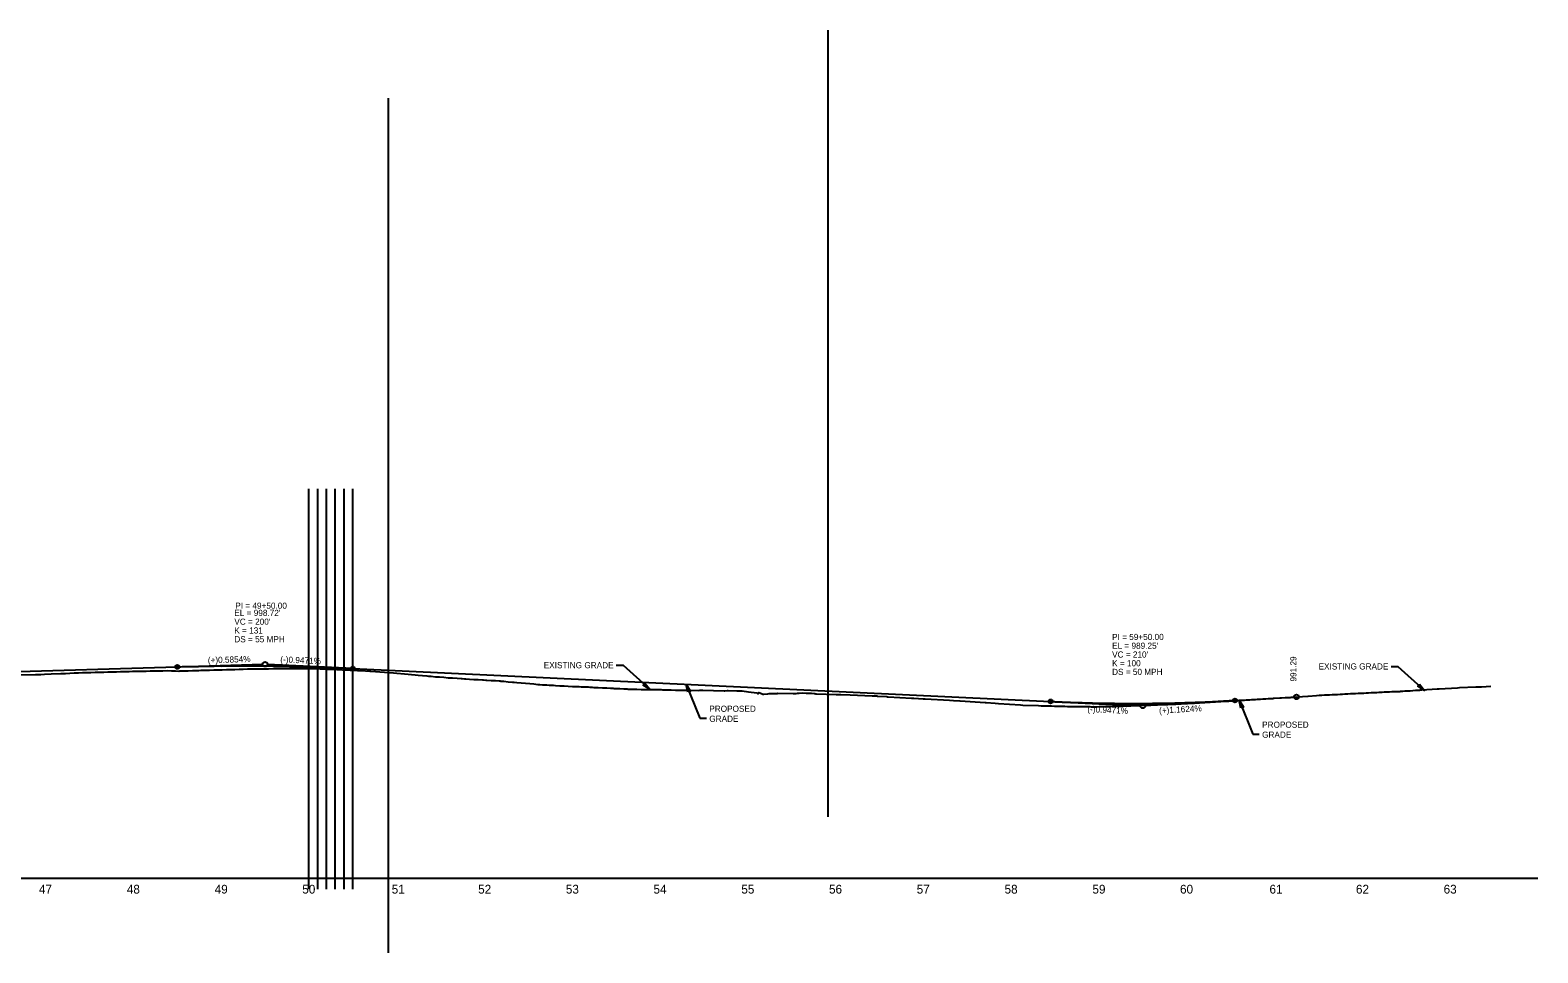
# Model space of a CAD drawing. Extents: x 1615624 to 1632571, y 894455 to 913418.
# Drawn here: x 1627212 to 1628930, y 901249 to 902300 of the extents above; entities that cross this region are included whole.
import ezdxf

# ---------------------------------------------------------------- set-up
doc = ezdxf.new("R2010")
doc.units = 0
for name, color, linetype in [('Default', 7, 'Continuous'), ('Exist Profile Cell', 7, 'Continuous'), ('Exist Vertical Profile Ground Line', 7, 'Continuous'), ('Exist Vertical Profile Horizontal Axis Label Major', 7, 'Continuous'), ('Prop Terminator CELL', 7, 'Continuous'), ('Prop Vertical Profile Curve Label', 7, 'Continuous'), ('Prop Vertical Profile Grade', 7, 'Continuous'), ('Prop Vertical Profile Grade Label', 7, 'Continuous'), ('Prop VPI Ditch Grade Right Label', 7, 'Continuous'), ('Prop VPI Label', 7, 'Continuous')]:
    doc.layers.add(name, color=color, linetype=linetype)

msp = doc.modelspace()

# ---------------------------------------------------------------- linework, layer by layer
at = {"layer": 'Default'}
for p, q in [((1628121.2, 902300.3), (1628121.2, 901404.2)), ((1627620.1, 902222.8), (1627620.1, 901249.4))]:
    msp.add_line(p, q, dxfattribs=at)
at = {"layer": 'Exist Profile Cell'}
for q in [(1628880.1, 901334.4), (1628929.9, 901334.4)]:
    msp.add_line((1623529.9, 901334.4), q, dxfattribs=at)
at = {"layer": 'Exist Vertical Profile Ground Line'}
msp.add_lwpolyline([(1627201.1, 901566.1), (1627218.2, 901566.6), (1627224.4, 901566.6), (1627228.7, 901566.8), (1627236.2, 901567), (1627247.2, 901567.4), (1627247.9, 901567.4), (1627252.7, 901567.7), (1627257.5, 901568), (1627262.3, 901568.3), (1627263.3, 901568.4), (1627263.7, 901568.4), (1627267.2, 901568.5), (1627272, 901568.6), (1627275.1, 901568.7), (1627276.8, 901568.7), (1627281.6, 901568.8), (1627286.4, 901569), (1627291.3, 901569.1), (1627296.3, 901569.2), (1627300.9, 901569.4), (1627305.7, 901569.5), (1627310.5, 901569.6), (1627315.3, 901569.8), (1627320.2, 901569.9), (1627323.6, 901569.9), (1627325, 901570), (1627328.9, 901570.1), (1627329.8, 901570.1), (1627334.6, 901570.2), (1627339.4, 901570.3), (1627344.5, 901570.4), (1627349.1, 901570.5), (1627351, 901570.5), (1627352.4, 901570.5), (1627353.9, 901570.5), (1627358.7, 901570.6), (1627363.5, 901570.7), (1627368.5, 901570.8), (1627373.2, 901570.6), (1627378, 901570.5), (1627381.7, 901570.4), (1627382.8, 901570.5), (1627384.3, 901570.5), (1627387.6, 901570.6), (1627392.4, 901570.7), (1627397.3, 901570.8), (1627402.1, 901571), (1627404.3, 901571), (1627406.9, 901571.2), (1627411.7, 901571.4), (1627412.1, 901571.4), (1627415.2, 901571.5), (1627416.5, 901571.5), (1627421.4, 901571.6), (1627423.9, 901571.7), (1627426.2, 901571.7), (1627430.1, 901571.8), (1627431, 901571.8), (1627435.8, 901572), (1627440.6, 901572.1), (1627445.4, 901572.3), (1627450.3, 901572.5), (1627454.5, 901572.6), (1627455.1, 901572.6), (1627459.9, 901572.7), (1627464.7, 901572.8), (1627467.5, 901572.9), (1627468.9, 901572.9), (1627469.5, 901572.9), (1627474.4, 901572.9), (1627479.2, 901573), (1627484, 901573), (1627488.6, 901573.1), (1627497.6, 901573.2), (1627504.5, 901573.2), (1627512.7, 901573.1), (1627519.1, 901573.1), (1627532.2, 901573.1), (1627542.8, 901572.8), (1627551.2, 901572.5), (1627555, 901572.4), (1627568, 901571.9), (1627585.2, 901571.1), (1627587, 901571), (1627594.2, 901570.5), (1627599.2, 901570.2), (1627600.6, 901570.1), (1627626.3, 901568.3), (1627629.9, 901568.1), (1627638.9, 901567.2), (1627651, 901566.1), (1627654.4, 901565.8), (1627659.3, 901565.3), (1627664.1, 901564.8), (1627666, 901564.7), (1627669, 901564.4), (1627673.9, 901563.9), (1627674.8, 901563.9), (1627678.8, 901563.6), (1627683.7, 901563.2), (1627688.6, 901562.8), (1627693.4, 901562.5), (1627698.6, 901562.1), (1627703.2, 901561.8), (1627704.3, 901561.7), (1627707.2, 901561.5), (1627708.1, 901561.4), (1627708.8, 901561.4), (1627713, 901561.1), (1627717.9, 901560.8), (1627722.8, 901560.6), (1627727.6, 901560.3), (1627728.7, 901560.2), (1627731.3, 901560), (1627732.5, 901560), (1627737.4, 901559.7), (1627740.7, 901559.5), (1627742.3, 901559.4), (1627746.5, 901559.1), (1627747.2, 901559.1), (1627747.6, 901559.1), (1627748.7, 901559), (1627752.1, 901558.7), (1627757, 901558.2), (1627761.8, 901557.7), (1627762.3, 901557.7), (1627763.1, 901557.6), (1627763.7, 901557.6), (1627766.7, 901557.3), (1627771.6, 901556.9), (1627776.5, 901556.4), (1627781.4, 901556), (1627786.3, 901555.6), (1627790.7, 901555.2), (1627791.1, 901555.1), (1627791.5, 901555.1), (1627793, 901555), (1627796, 901554.8), (1627800.9, 901554.5), (1627803.7, 901554.3), (1627805.8, 901554.2), (1627807.6, 901554.2), (1627808.6, 901554.1), (1627810.7, 901554), (1627815.6, 901553.7), (1627820.5, 901553.4), (1627825.3, 901553.1), (1627830.2, 901552.8), (1627831.8, 901552.7), (1627834.4, 901552.6), (1627835.1, 901552.6), (1627837.7, 901552.6), (1627840, 901552.5), (1627844.9, 901552.3), (1627846.8, 901552.2), (1627848, 901552.2), (1627849.8, 901552.1), (1627850.8, 901552), (1627852.5, 901551.9), (1627854.6, 901551.8), (1627859.5, 901551.6), (1627864.4, 901551.4), (1627869.3, 901551.2), (1627873.5, 901551), (1627874.2, 901550.9), (1627876.6, 901550.7), (1627877.7, 901550.6), (1627879.1, 901550.6), (1627880.8, 901550.5), (1627884, 901550.4), (1627888.8, 901550.2), (1627889.3, 901550.2), (1627892.5, 901550), (1627893.7, 901549.9), (1627894.8, 901549.9), (1627898.6, 901549.8), (1627903.5, 901549.6), (1627908.4, 901549.4), (1627913.3, 901549.3), (1627915.4, 901549.2), (1627918.1, 901549.4), (1627918.6, 901549.4), (1627919.3, 901549.4), (1627922.3, 901549.3), (1627923, 901549.3), (1627927.9, 901549.2), (1627931.1, 901549.2), (1627932.8, 901549.1), (1627933.6, 901549.1), (1627936.9, 901548.9), (1627937.7, 901548.9), (1627942.6, 901548.8), (1627947.5, 901548.7), (1627958.1, 901548.6), (1627961.1, 901548.5), (1627963.8, 901548.5), (1627973.2, 901548.3), (1627975.4, 901548.5), (1627975.8, 901548.5), (1627977, 901548.6), (1627978.6, 901548.6), (1628003, 901548), (1628003.9, 901548), (1628006.4, 901548.2), (1628007.4, 901548.1), (1628017.2, 901547.9), (1628021.6, 901547.9), (1628023.5, 901547.7), (1628030.6, 901546.8), (1628040.3, 901545.5), (1628041.4, 901544.4), (1628042.6, 901545.9), (1628045.6, 901544.9), (1628046.9, 901544.2), (1628047.5, 901544), (1628048.1, 901544), (1628052.8, 901544.5), (1628054.4, 901544.6), (1628056.4, 901544.6), (1628062.6, 901544.8), (1628063.4, 901544.9), (1628064, 901545), (1628081.6, 901544.7), (1628084.9, 901544.9), (1628086.4, 901545), (1628087.7, 901545.1), (1628088.5, 901545.2), (1628091.8, 901545.4), (1628096.3, 901545.2), (1628102.6, 901545), (1628105.6, 901544.7), (1628106.3, 901544.6), (1628107.3, 901544.5), (1628108.3, 901544.5), (1628130.6, 901543.8), (1628131.4, 901543.8), (1628132.2, 901543.8), (1628135.9, 901543.6), (1628146.4, 901543.2), (1628171.4, 901542.2), (1628176.6, 901542.1), (1628176.9, 901542), (1628177.5, 901541.9), (1628178.1, 901541.9), (1628187.8, 901541.2), (1628188.2, 901541.2), (1628188.9, 901541.1), (1628189.7, 901541.1), (1628216.2, 901539.4), (1628217.9, 901539.4), (1628219.1, 901539.4), (1628229.6, 901538.8), (1628231.9, 901538.7), (1628259.8, 901537), (1628264.4, 901536.8), (1628271.3, 901536.3), (1628271.8, 901536.3), (1628300.4, 901534.5), (1628301.5, 901534.4), (1628311.6, 901533.7), (1628315.6, 901533.4), (1628340.5, 901531.8), (1628343.4, 901531.6), (1628361, 901531), (1628364, 901530.9), (1628365.2, 901530.9), (1628367, 901530.8), (1628370, 901530.7), (1628373, 901530.6), (1628373.4, 901530.6), (1628376, 901530.6), (1628379.1, 901530.5), (1628382.2, 901530.4), (1628385.1, 901530.3), (1628386.4, 901530.2), (1628388.1, 901530.2), (1628391.1, 901530.2), (1628394.1, 901530.1), (1628394.5, 901530.1), (1628397.1, 901530.1), (1628399.3, 901530), (1628400.1, 901530), (1628403.1, 901530), (1628406.2, 901530), (1628406.8, 901529.9), (1628409.2, 901529.9), (1628412.2, 901529.9), (1628415.2, 901529.8), (1628418.2, 901529.8), (1628419.4, 901529.8), (1628421.2, 901529.7), (1628424.2, 901529.7), (1628426.1, 901529.7), (1628427.2, 901529.7), (1628430.2, 901529.8), (1628432.4, 901529.8), (1628433.2, 901529.8), (1628436.3, 901529.8), (1628439.3, 901529.9), (1628440, 901529.9), (1628442.3, 901530), (1628445.3, 901530.2), (1628446, 901530.2), (1628448.3, 901530.3), (1628451.3, 901530.3), (1628454.3, 901530.4), (1628455.9, 901530.5), (1628457.3, 901530.6), (1628460.5, 901530.7), (1628463.4, 901530.8), (1628466.4, 901530.9), (1628469.4, 901531), (1628471.8, 901531.1), (1628472.4, 901531.1), (1628475.4, 901531.3), (1628475.8, 901531.3), (1628478.4, 901531.4), (1628481.4, 901531.5), (1628484.4, 901531.6), (1628487.4, 901531.7), (1628490.4, 901531.7), (1628493.5, 901531.8), (1628494.5, 901531.9), (1628496.5, 901532), (1628499.5, 901532.1), (1628502.5, 901532.2), (1628503.7, 901532.2), (1628505.5, 901532.3), (1628508.5, 901532.4), (1628511.5, 901532.5), (1628512.7, 901532.6), (1628514.5, 901532.7), (1628514.9, 901532.7), (1628517.5, 901532.8), (1628520.6, 901533), (1628523.6, 901533.1), (1628526.6, 901533.3), (1628529.6, 901533.4), (1628530.9, 901533.5), (1628532.6, 901533.6), (1628535.6, 901533.8), (1628537, 901533.8), (1628538.6, 901533.9), (1628541.6, 901534.1), (1628544.6, 901534.3), (1628547.6, 901534.5), (1628549.5, 901534.6), (1628550.7, 901534.6), (1628553.7, 901534.8), (1628556.7, 901535), (1628559.1, 901535.1), (1628559.7, 901535.2), (1628562.7, 901535.4), (1628565.7, 901535.5), (1628568.7, 901535.7), (1628571.7, 901535.9), (1628574.7, 901536.1), (1628577.8, 901536.2), (1628580.8, 901536.4), (1628581.7, 901536.5), (1628583.8, 901536.6), (1628586.8, 901536.8), (1628588.2, 901536.9), (1628589.8, 901537), (1628592.8, 901537.1), (1628595.8, 901537.3), (1628598.8, 901537.5), (1628601.8, 901537.7), (1628604.2, 901537.8), (1628604.8, 901537.8), (1628607.9, 901538), (1628608.2, 901538), (1628610.9, 901538.2), (1628613.9, 901538.4), (1628616.9, 901538.6), (1628619.9, 901538.7), (1628622.9, 901538.9), (1628625.9, 901539.1), (1628627.9, 901539.2), (1628628.9, 901539.3), (1628647.3, 901540.4), (1628648, 901540.4), (1628661.7, 901541.3), (1628667.8, 901541.8), (1628668.2, 901541.8), (1628677.9, 901542.5), (1628680.9, 901542.7), (1628683.9, 901542.9), (1628686.8, 901543.1), (1628689, 901543.2), (1628689.6, 901543.2), (1628692.7, 901543.4), (1628695.7, 901543.6), (1628698.7, 901543.7), (1628701.6, 901543.8), (1628704.6, 901544), (1628707.5, 901544.1), (1628710, 901544.3), (1628710.7, 901544.3), (1628713.4, 901544.4), (1628716.4, 901544.6), (1628719.4, 901544.7), (1628722.3, 901544.9), (1628725.3, 901545), (1628728.2, 901545.1), (1628731.2, 901545.3), (1628731.6, 901545.3), (1628734.2, 901545.4), (1628737.1, 901545.6), (1628740.1, 901545.8), (1628743, 901545.9), (1628746, 901546.1), (1628746.5, 901546.1), (1628748.9, 901546.2), (1628751.9, 901546.3), (1628752.2, 901546.4), (1628752.7, 901546.4), (1628754.9, 901546.5), (1628757.8, 901546.6), (1628760.8, 901546.7), (1628763.7, 901546.9), (1628766.7, 901547), (1628769.7, 901547.1), (1628772.6, 901547.2), (1628773.5, 901547.3), (1628775.6, 901547.5), (1628776.2, 901547.5), (1628778.5, 901547.7), (1628781.5, 901547.8), (1628784.4, 901548), (1628787.4, 901548.2), (1628790.4, 901548.4), (1628793.3, 901548.6), (1628795.4, 901548.7), (1628795.8, 901548.8), (1628796.4, 901548.8), (1628797.8, 901548.9), (1628815.2, 901550), (1628817.6, 901550.1), (1628838.3, 901551.4), (1628840.6, 901551.5), (1628859.4, 901552.3), (1628865.9, 901552.5), (1628876.3, 901553)], dxfattribs=at)
at = {"layer": 'Prop Terminator CELL'}
for points in [[(1627912.6, 901556.7), (1627918.2, 901549.6), (1627910.5, 901554.4), (1627912.4, 901554.8)], [(1627961.7, 901546.3), (1627959.8, 901555.2), (1627964.6, 901547.4), (1627962.7, 901547.9)], [(1628795.3, 901555.3), (1628800.9, 901548.1), (1628793.2, 901553), (1628795.1, 901553.4)], [(1628591.6, 901528.1), (1628589.7, 901537.1), (1628594.5, 901529.3), (1628592.6, 901529.7)]]:
    msp.add_lwpolyline(points, close=True, dxfattribs=at)
at = {"layer": 'Prop Vertical Profile Curve Label'}
for centre in [(1627379.9, 901575.1), (1627579.9, 901573.3), (1628374.9, 901535.7), (1628584.9, 901536.8)]:
    msp.add_circle(centre, 2.25, dxfattribs=at)
at = {"layer": 'Prop Vertical Profile Grade'}
for p, q in [((1626959.9, 901562.8), (1627379.9, 901575.1)), ((1627579.9, 901573.3), (1628374.9, 901535.7)), ((1628584.9, 901536.8), (1628654.9, 901540.9))]:
    msp.add_line(p, q, dxfattribs=at)
for points in [[(1627379.9, 901575.1), (1627383.9, 901575.3), (1627387.9, 901575.4), (1627391.9, 901575.5), (1627395.9, 901575.6), (1627399.9, 901575.6), (1627403.9, 901575.7), (1627407.9, 901575.8), (1627411.9, 901575.9), (1627415.9, 901575.9), (1627419.9, 901576), (1627423.9, 901576.1), (1627427.9, 901576.1), (1627431.9, 901576.1), (1627435.9, 901576.2), (1627439.9, 901576.2), (1627443.9, 901576.2), (1627447.9, 901576.2), (1627451.9, 901576.3), (1627455.9, 901576.3), (1627459.9, 901576.3), (1627463.9, 901576.2), (1627467.9, 901576.2), (1627471.9, 901576.2), (1627475.9, 901576.2), (1627479.9, 901576.2), (1627483.9, 901576.1), (1627487.9, 901576.1), (1627491.9, 901576), (1627495.9, 901576), (1627499.9, 901575.9), (1627503.9, 901575.8), (1627507.9, 901575.7), (1627511.9, 901575.7), (1627515.9, 901575.6), (1627519.9, 901575.5), (1627523.9, 901575.4), (1627527.9, 901575.3), (1627531.9, 901575.2), (1627535.9, 901575), (1627539.9, 901574.9), (1627543.9, 901574.8), (1627547.9, 901574.6), (1627551.9, 901574.5), (1627555.9, 901574.4), (1627559.9, 901574.2), (1627563.9, 901574), (1627567.9, 901573.9), (1627571.9, 901573.7), (1627575.9, 901573.5), (1627579.9, 901573.3)], [(1628374.9, 901535.7), (1628379.1, 901535.5), (1628383.3, 901535.3), (1628387.5, 901535.1), (1628391.7, 901535), (1628395.9, 901534.8), (1628400.1, 901534.6), (1628404.3, 901534.5), (1628408.5, 901534.4), (1628412.7, 901534.3), (1628416.9, 901534.1), (1628421.1, 901534), (1628425.3, 901533.9), (1628429.5, 901533.8), (1628433.7, 901533.8), (1628437.9, 901533.7), (1628442.1, 901533.6), (1628446.3, 901533.6), (1628450.5, 901533.5), (1628454.7, 901533.5), (1628458.9, 901533.5), (1628463.1, 901533.5), (1628467.3, 901533.5), (1628471.5, 901533.5), (1628475.7, 901533.5), (1628479.9, 901533.5), (1628484.1, 901533.5), (1628488.3, 901533.5), (1628492.5, 901533.6), (1628496.7, 901533.6), (1628500.9, 901533.7), (1628505.1, 901533.8), (1628509.3, 901533.9), (1628513.5, 901533.9), (1628517.7, 901534), (1628521.9, 901534.1), (1628526.1, 901534.3), (1628530.3, 901534.4), (1628534.5, 901534.5), (1628538.7, 901534.7), (1628542.9, 901534.8), (1628547.1, 901535), (1628551.3, 901535.1), (1628555.5, 901535.3), (1628559.7, 901535.5), (1628563.9, 901535.7), (1628568.1, 901535.9), (1628572.3, 901536.1), (1628576.5, 901536.3), (1628580.7, 901536.6), (1628584.9, 901536.8)]]:
    msp.add_spline(points, degree=3, dxfattribs=at)
at = {"layer": 'Prop VPI Ditch Grade Right Label'}
for p, q in [((1627529.9, 901321.9), (1627529.9, 901777.7)), ((1627539.9, 901321.9), (1627539.9, 901777.7)), ((1627549.9, 901321.9), (1627549.9, 901777.7)), ((1627559.9, 901321.9), (1627559.9, 901777.7)), ((1627569.9, 901321.9), (1627569.9, 901777.7)), ((1627579.9, 901321.9), (1627579.9, 901777.7))]:
    msp.add_line(p, q, dxfattribs=at)
at = {"layer": 'Prop VPI Label'}
for p, q in [((1627379.9, 901575.1), (1627477.2, 901578)), ((1627579.9, 901573.3), (1627482.7, 901577.9)), ((1627888.3, 901576.6), (1627880.1, 901576.6)), ((1627918.2, 901549.6), (1627888.3, 901576.6)), ((1628771, 901575.1), (1628762.8, 901575.1)), ((1628800.9, 901548.1), (1628771, 901575.1)), ((1627959.8, 901555.2), (1627975.3, 901516.5)), ((1628374.9, 901535.7), (1628477.2, 901530.8)), ((1628584.9, 901536.8), (1628482.7, 901530.9)), ((1628589.7, 901537.1), (1628605.1, 901498.3)), ((1627975.3, 901516.5), (1627982.7, 901516.5)), ((1628605.1, 901498.3), (1628612.6, 901498.3))]:
    msp.add_line(p, q, dxfattribs=at)
for centre in [(1627479.9, 901578.1), (1628479.9, 901530.7), (1628654.9, 901540.9)]:
    msp.add_circle(centre, 2.75, dxfattribs=at)

# ---------------------------------------------------------------- texts
at = {"layer": 'Exist Vertical Profile Horizontal Axis Label Major'}
for s, p in [('47', (1627222.3, 901316.9)), ('48', (1627322.4, 901316.9)), ('49', (1627422.5, 901316.9)), ('50', (1627522.3, 901316.9)), ('51', (1627624.2, 901316.9)), ('52', (1627722.7, 901316.9)), ('53', (1627822.6, 901316.9)), ('54', (1627922.4, 901316.9)), ('55', (1628022.5, 901316.9)), ('56', (1628122.4, 901316.9)), ('57', (1628222.3, 901316.9)), ('58', (1628322.4, 901316.9)), ('59', (1628422.5, 901316.9)), ('60', (1628522.3, 901316.9)), ('61', (1628624.2, 901316.9)), ('62', (1628722.7, 901316.9)), ('63', (1628822.6, 901316.9))]:
    msp.add_text(s, height=10, dxfattribs=at).set_placement(p)
at = {"layer": 'Prop Vertical Profile Curve Label'}
for s, p in [("VC = 200'", (1627444.9, 901623.1)), ("VC = 210'", (1628444.9, 901585.7)), ('K = 100', (1628444.9, 901575.8)), ('DS = 50 MPH', (1628444.9, 901565.9))]:
    msp.add_text(s, height=7, dxfattribs=at).set_placement(p)
at = {"layer": 'Prop Vertical Profile Grade Label'}
for s, rotation, p in [('(+)0.5854%', 1.6766, (1627414.8, 901579.2)), ('(-)0.9471%', 357.2888, (1627497.1, 901580.3)), ('(+)1.1624%', 3.3263, (1628498.6, 901521.8)), ('(-)0.9471%', 357.2888, (1628416.6, 901523.7))]:
    msp.add_text(s, height=7, rotation=rotation, dxfattribs=at).set_placement(p)
at = {"layer": 'Prop VPI Label'}
for s, p in [("EL = 998.72'", (1627444.9, 901633.1)), ('PI = 49+50.00', (1627446, 901641.3)), ('K = 131', (1627444.9, 901613.1)), ('DS = 55 MPH', (1627444.9, 901603.1)), ('PI = 59+50.00', (1628444.9, 901605.7)), ("EL = 989.25'", (1628444.9, 901595.7)), ('EXISTING GRADE', (1627797.4, 901573.5)), ('EXISTING GRADE', (1628680.1, 901572.1)), ('GRADE', (1627986, 901512.5)), ('PROPOSED ', (1627986, 901523.9)), ('GRADE', (1628615.8, 901494.4)), ('PROPOSED ', (1628615.8, 901505.8))]:
    msp.add_text(s, height=7, dxfattribs=at).set_placement(p)
msp.add_text('991.29', height=7, rotation=90, dxfattribs=at).set_placement((1628654.9, 901558.4))

doc.saveas('drawing.dxf')
